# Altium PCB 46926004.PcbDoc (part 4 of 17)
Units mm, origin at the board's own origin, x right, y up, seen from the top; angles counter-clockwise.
Board outline 250 x 200 mm, 6 copper layers (Top Layer, INT1_GND, INT2_SIG, INT3_SIG, INT4_GND, Bottom Layer), stack 1.71 mm thick; 1450 components, 1293 nets, 5656 pads, 2307 vias.
Unrouted connection lines stored in the file: 2.
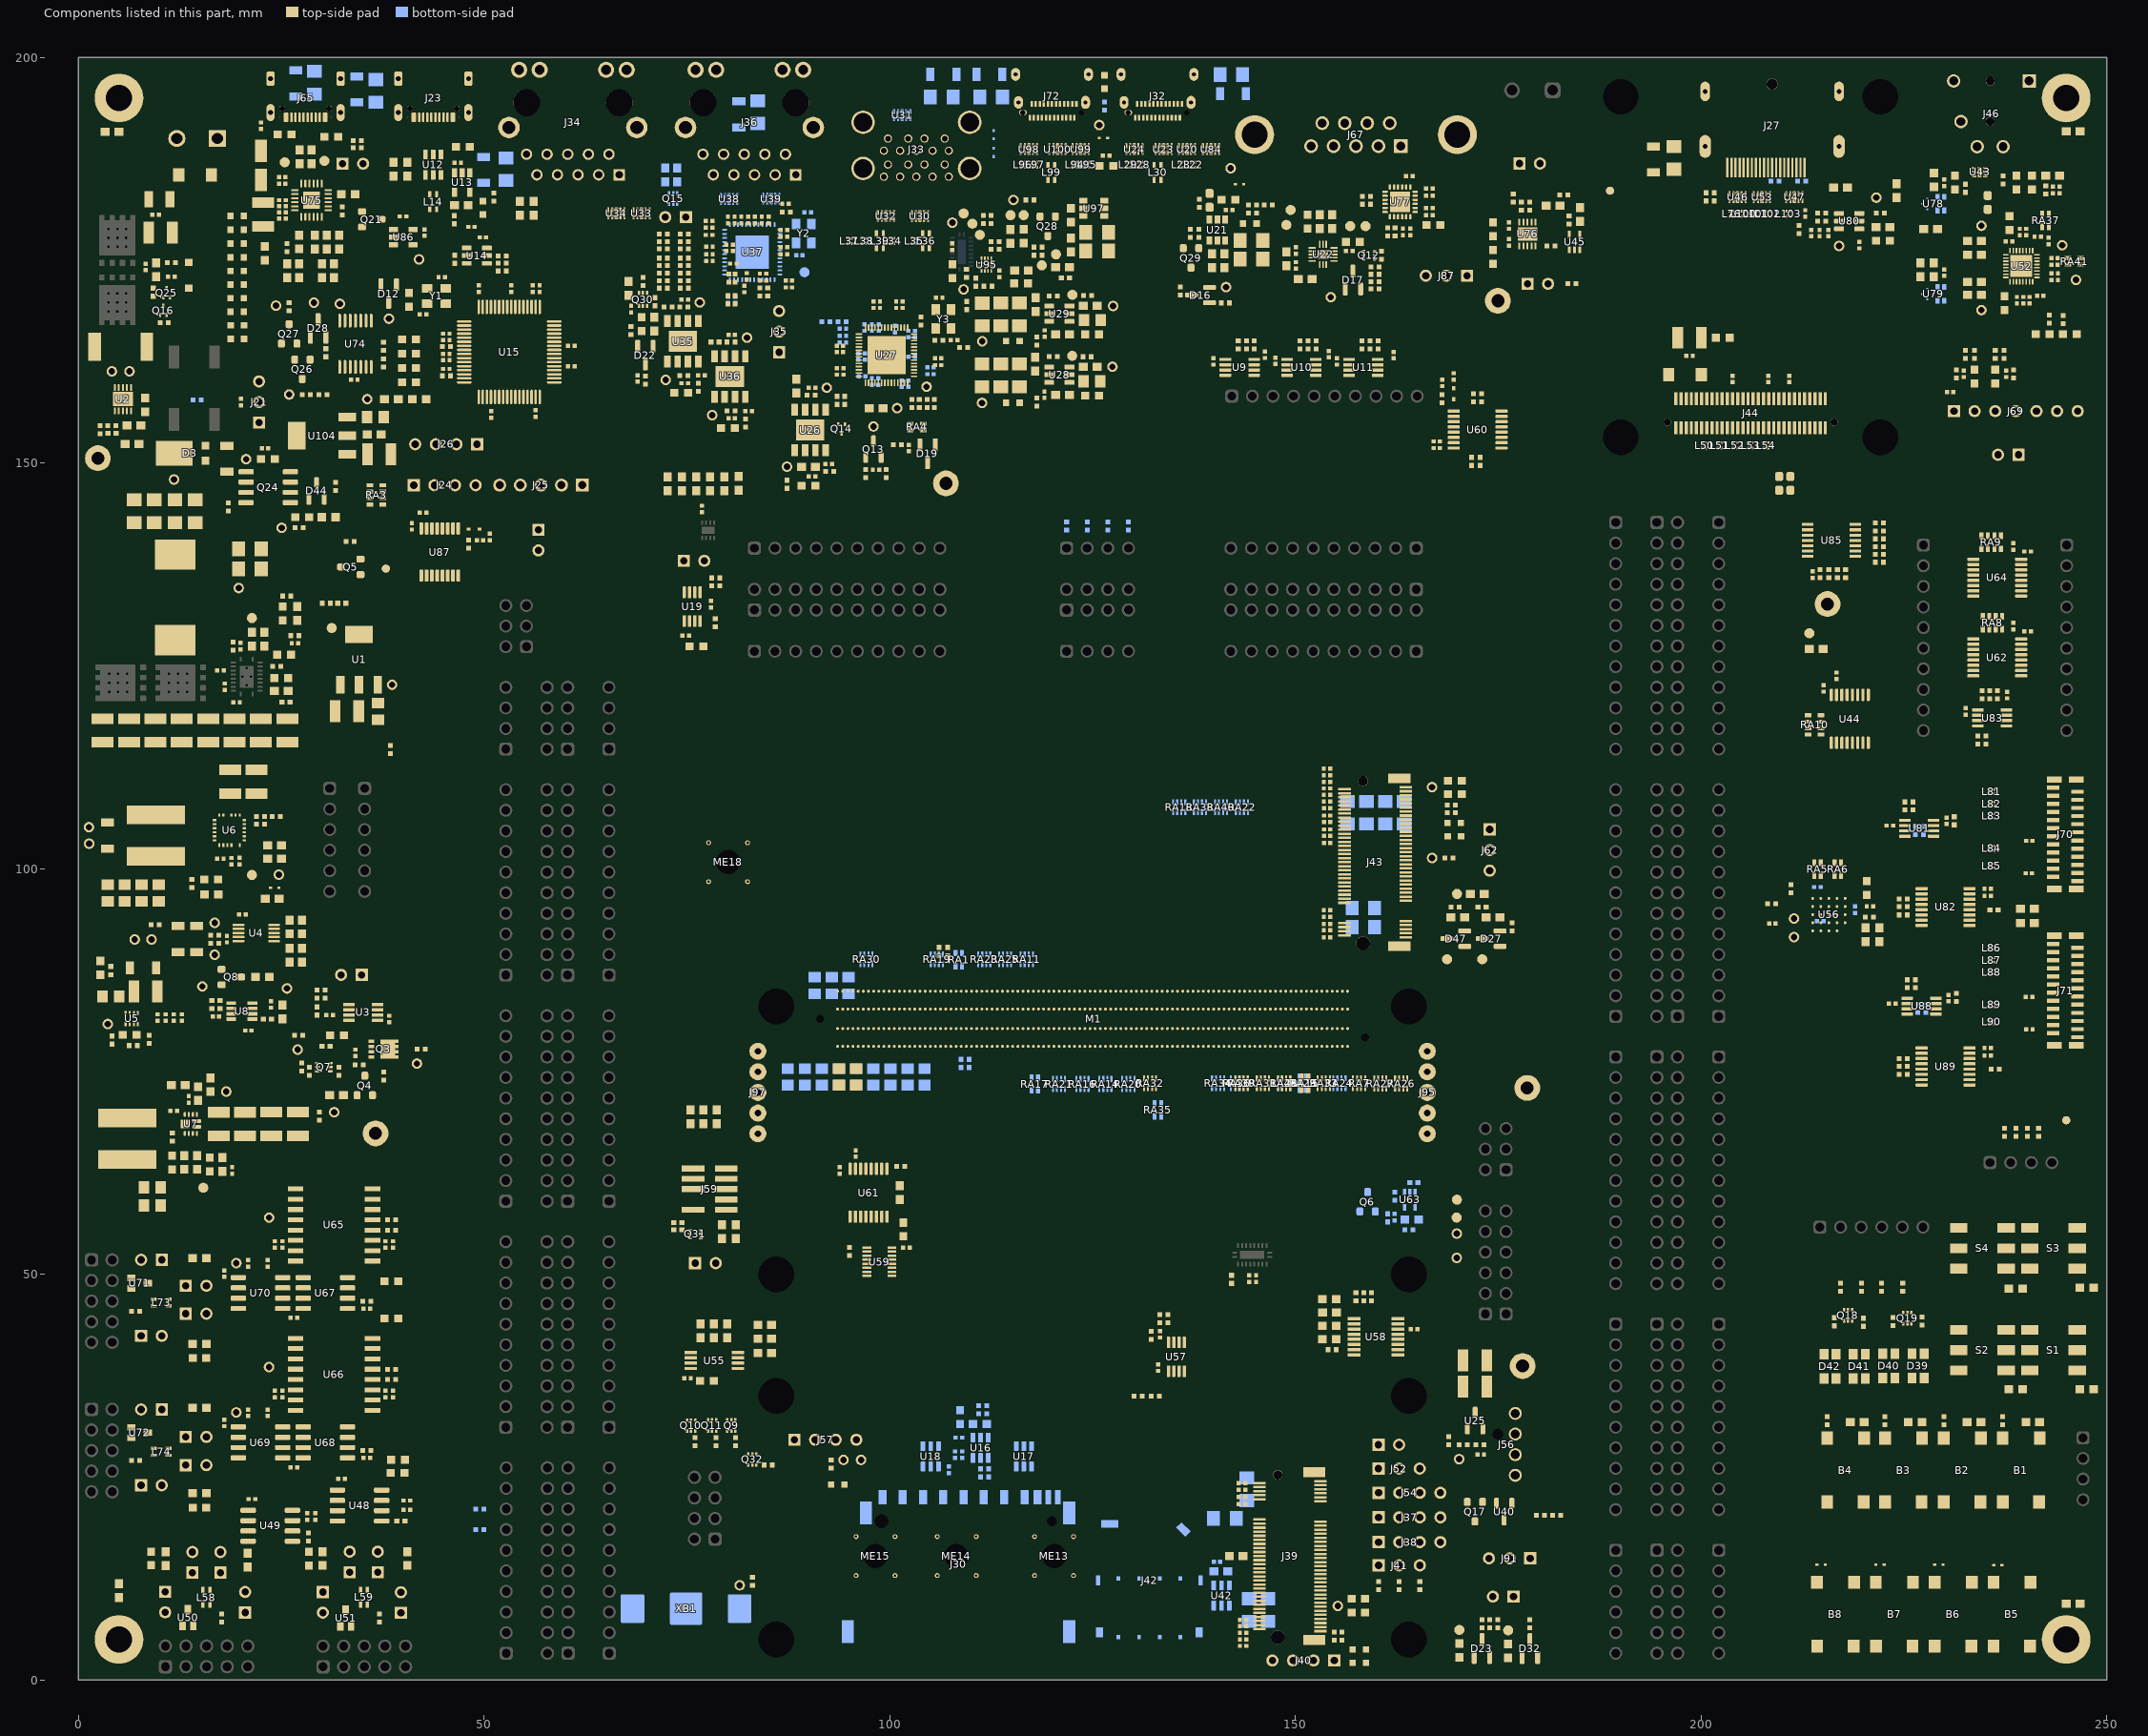
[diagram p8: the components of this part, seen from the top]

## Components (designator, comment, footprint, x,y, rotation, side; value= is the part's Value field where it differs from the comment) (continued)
XB1 "3030TR" T_KEYSTONE_3030 74.9,8.8 r0 bottom locked
Y1 "0986-Xtal 12MHz 3.2x2.5mm" XTAL_CX3225 44.14,170.6 r0 top value="12 MHz"
Y2 "0987-Xtal 25MHz 3.2x2.5mm" XTAL_CX3225 89.397,178.29 r270 bottom value="25 MHz"
Y3 "0987-Xtal 25MHz 3.2x2.5mm" XTAL_CX3225 106.617,167.768 r90 top value="25 MHz"

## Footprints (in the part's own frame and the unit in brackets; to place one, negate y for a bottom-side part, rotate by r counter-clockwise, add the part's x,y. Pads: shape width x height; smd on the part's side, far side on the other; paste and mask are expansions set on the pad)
3M-SJ61A3 [mm] "BUMPER CYLIN 0.375\"(9.53mm) DIA BLK, Thickness: 0.250\" (6.35mm)"
  silkscreen extent -4.67,-4.67 4.85,4.85, body extent -4.76,-4.76 4.76,4.76, height 6.38
4-PLCC [mm] "LED RGB DIFFUSED 4PLCC SMD 3.2 x 2.8 x 1.9 mm"
  rect 1.1x1.3 smd: 1(-0.75,-1.5) 2(-0.75,1.5) 3(0.75,1.5) 4(0.75,-1.5)
  silkscreen extent -1.66,-1.56 1.4,0.51, body extent -1.39,-1.75 1.41,1.75, height 1.9
"10-DFN (3X3)_ADI" [mil] "10-Lead Plastic DFN (3mm ? 3mm), 10-WFDFN Exposed Pad"
  rect 32x10 smd paste+0 mask+0: 1(-57,39.37) 2(-57,19.68) 3(-57,0) 4(-57,-19.69) 5(-57,-39.37) 6(57,-39.37) 7(57,-19.69) 8(57,0) 9(57,19.68) 10(57,39.37)
  rect 69x98 smd paste+0 mask+0: 11(0,0)
  silkscreen extent -93,-66 66,66, body extent -59,-59 59,59, height 30
10-UFDFN [mm] "TVS Diode Surface Mount U-DFN2510-10 (2.5x1.0mm)"
  rrect50% 0.625x0.25 smd mask+0.05: 1(-0.417,1) 2(-0.417,0.5) 4(-0.417,-0.5) 5(-0.417,-1) 6(0.417,-1) 7(0.417,-0.5) 9(0.417,0.5) 10(0.417,1)
  rrect50% 0.7x0.45 smd mask+0.102: 3(-0.375,0)
  rrect50% 0.575x0.45 smd mask+0.102: 8(0.442,0)
  silkscreen extent -1.08,-1.35 0.56,1.36, body extent -0.5,-1.25 0.5,1.25, height 0.5
"10-VSON (3X3)" [mil] "10-VFDFN Exposed Pad, DRC (TI)"
  rect 32x10 smd paste+0 mask+0: 1(-57,39.37) 2(-57,19.68) 3(-57,0) 4(-57,-19.68) 5(-57,-39.37) 6(57,-39.37) 7(57,-19.68) 8(57,0) 9(57,19.68) 10(57,39.37)
  rect 65x95 smd paste-47 mask-47: 11(0,0)
  silkscreen extent -90,-66 66,66, body extent -59,-59 59,59, height 39
"11-VQFN-HR (2.5X2)" [mm] "2.0-mm x 2.5-mm VQFN HotRod Package (TI)"
  rrect40% 0.55x0.25 smd mask+0: 1(-1.175,0.75) 2(-1.175,0.25) 3(-1.175,-0.25) 4(-1.175,-0.75) 7(1.175,-0.75) 8(1.175,-0.25) 9(1.175,0.25) 10(1.175,0.75)
  rrect45% 0.45x1.1 smd paste-2 mask+0: 5(-0.35,-0.7) 6(0.35,-0.7)
  rrect19% 1.1x1.1 smd paste-2 mask+0: 11(0,0.7)
  silkscreen extent -1.89,-1.2 1.25,1.2, body extent -1.25,-1 1.25,1, height 1
"12-X2QFN (1.6X1.6)" [mm] "12-XFQFN 1.60 mm ? 1.60 mm, RWB0012A (TI)"
  rrect50% 0.7x0.2 smd paste+0 mask+0.051: 1(-0.65,0.2) 2(-0.65,-0.2) 7(0.65,-0.2) 8(0.65,0.2)
  rrect50% 0.2x0.5 smd paste+0 mask+0.051: 3(-0.6,-0.75) 4(-0.2,-0.75) 5(0.2,-0.75) 6(0.6,-0.75) 9(0.6,0.75) 10(0.2,0.75) 11(-0.2,0.75) 12(-0.6,0.75)
  silkscreen extent -0.96,-0.91 0.92,0.91, body extent -0.8,-0.8 0.8,0.8, height 0.4
16-SSOP_DBQ_TI [mm] "16-SSOP (0.154\", 3.90mm Width), MO-137"
  rect 1.6x0.41 smd: 1(-2.7,2.223) 2(-2.7,1.588) 3(-2.7,0.953) 4(-2.7,0.317) 5(-2.7,-0.318) 6(-2.7,-0.953) 7(-2.7,-1.588) 8(-2.7,-2.223) 9(2.7,-2.223) 10(2.7,-1.588) 11(2.7,-0.953) 12(2.7,-0.317) 13(2.7,0.318) 14(2.7,0.953) 15(2.7,1.588) 16(2.7,2.223)
  silkscreen extent -1.55,-2.49 1.55,2.49, body extent -3,-2.45 3,2.45, height 1.75
"56-VQFN (7X7)" [mm] "56-VFQFN Exposed Pad, 0.4 mm pitch"
  rrect50% 0.808x0.204 smd paste+0 mask+0: 1(-3.401,2.6) 2(-3.401,2.2) 3(-3.401,1.8) 4(-3.401,1.4) 5(-3.401,1) 6(-3.401,0.6) 7(-3.401,0.2) 8(-3.401,-0.2) 9(-3.401,-0.6) 10(-3.401,-1) 11(-3.401,-1.4) 12(-3.401,-1.8) 13(-3.401,-2.2) 14(-3.401,-2.6) 29(3.401,-2.6) 30(3.401,-2.2) 31(3.401,-1.8) 32(3.401,-1.4) 33(3.401,-1) 34(3.401,-0.6) 35(3.401,-0.2) 36(3.401,0.2) 37(3.401,0.6) 38(3.401,1) 39(3.401,1.4) 40(3.401,1.8) 41(3.401,2.2) 42(3.401,2.6)
  rrect50% 0.204x0.808 smd paste+0 mask+0: 15(-2.6,-3.401) 16(-2.2,-3.401) 17(-1.8,-3.401) 18(-1.4,-3.401) 19(-1,-3.401) 20(-0.6,-3.401) 21(-0.2,-3.401) 22(0.2,-3.401) 23(0.6,-3.401) 24(1,-3.401) 25(1.4,-3.401) 26(1.8,-3.401) 27(2.2,-3.401) 28(2.6,-3.401) 43(2.6,3.401) 44(2.2,3.401) 45(1.8,3.401) 46(1.4,3.401) 47(1,3.401) 48(0.6,3.401) 49(0.2,3.401) 50(-0.2,3.401) 51(-0.6,3.401) 52(-1,3.401) 53(-1.4,3.401) 54(-1.8,3.401) 55(-2.2,3.401) 56(-2.6,3.401)
  rect 4.699x4.699 smd paste-2.349 mask+0: 57(0,0)
  silkscreen extent -4.24,-4.21 4.21,4.21, body extent -3.5,-3.5 3.5,3.5, height 0.99
AMPHENOL_12401826E412A [mm]
  round 0.325 hole 0.65 unplated: 0(-3.6,2.02)
  oval 0.95x0.65 hole 0.65 slot 0.95 at 0 deg unplated: 0(3.6,2.02)
  rect 0.3x0.7 smd: A1(-2.75,2.68) A2(-2.25,2.68) A3(-1.75,2.68) A4(-1.25,2.68) A5(-0.75,2.68) A6(-0.25,2.68) A7(0.25,2.68) A8(0.75,2.68) A9(1.25,2.68) A10(1.75,2.68) A11(2.25,2.68) A12(2.75,2.68) B1(2.5,0.98) B2(2,0.98) B3(1.5,0.98) B4(1,0.98) B5(0.5,0.98) B6(0,0.98) B7(-0.5,0.98) B8(-1,0.98) B9(-1.5,0.98) B10(-2,0.98) B11(-2.5,0.98) B12(-3,0.98)
  oval 1.1x1.6 hole 0.5 slot 1.1 at 90 deg paste+0: SH1(-4.13,0.77) SH3(4.49,-2.68) SH4(-4.49,-2.68)
  oval 1.1x1.55 hole 0.5 slot 1.1 at 90 deg paste+0: SH2(4.13,0.77)
  Top Layer keep-out region: -3.75,-5.22 3.75,-5.22 3.75,-0.25 -3.75,-0.25
  silkscreen extent -4.6,-4.33 4.6,3.58, body extent -4.61,-7.56 4.59,2.94, height 3.2
AMPHENOL_MDT275B03001_TYPE_3052 [mm] "PCIe M.2 Connectors, Storage and Server Connector, P=0.5mm, H=2.75mm, Key B, Gold Plating"
  rect 0.3x1.55 smd mask+0.05: 1(-9.25,3.775) 2(-9,-3.775) 3(-8.75,3.775) 4(-8.5,-3.775) 5(-8.25,3.775) 6(-8,-3.775) 7(-7.75,3.775) 8(-7.5,-3.775) 9(-7.25,3.775) 10(-7,-3.775) 11(-6.75,3.775) 20(-4.5,-3.775) 21(-4.25,3.775) 22(-4,-3.775) 23(-3.75,3.775) 24(-3.5,-3.775) 25(-3.25,3.775) 26(-3,-3.775) 27(-2.75,3.775) 28(-2.5,-3.775) 29(-2.25,3.775) 30(-2,-3.775) 31(-1.75,3.775) 32(-1.5,-3.775) 33(-1.25,3.775) 34(-1,-3.775) 35(-0.75,3.775) 36(-0.5,-3.775) 37(-0.25,3.775) 38(0,-3.775) 39(0.25,3.775) 40(0.5,-3.775) 41(0.75,3.775) 42(1,-3.775) 43(1.25,3.775) 44(1.5,-3.775) 45(1.75,3.775) 46(2,-3.775) 47(2.25,3.775) 48(2.5,-3.775) 49(2.75,3.775) 50(3,-3.775) 51(3.25,3.775) 52(3.5,-3.775) 53(3.75,3.775) 54(4,-3.775) 55(4.25,3.775) 56(4.5,-3.775) 57(4.75,3.775) 58(5,-3.775) 59(5.25,3.775) 60(5.5,-3.775) 61(5.75,3.775) 62(6,-3.775) 63(6.25,3.775) 64(6.5,-3.775) 65(6.75,3.775) 66(7,-3.775) 67(7.25,3.775) 68(7.5,-3.775) 69(7.75,3.775) 70(8,-3.775) 71(8.25,3.775) 72(8.5,-3.775) 73(8.75,3.775) 74(9,-3.775) 75(9.25,3.775)
  rect 1.2x2.75 smd mask+0.05: P1(-10.35,3) P2(10.35,3)
  round 1.15 hole 1.15 unplated: ""(-10,-1.5)
  round 1.65 hole 1.65 unplated: ""(10,-1.5)
  silkscreen extent -15,-51.75 15,4.9, body extent -15,-41.75 15,4.2, height 3.19
AMPHENOL_MDT420M01501 [mm] "CONN M.2 Gen 5 FEMALE 75POS 0.020 GOLD H=4.2mm"
  rect 0.3x1.55 smd mask+0.05: 1(-9.25,3.775) 2(-9,-3.775) 3(-8.75,3.775) 4(-8.5,-3.775) 5(-8.25,3.775) 6(-8,-3.775) 7(-7.75,3.775) 8(-7.5,-3.775) 9(-7.25,3.775) 10(-7,-3.775) 11(-6.75,3.775) 12(-6.5,-3.775) 13(-6.25,3.775) 14(-6,-3.775) 15(-5.75,3.775) 16(-5.5,-3.775) 17(-5.25,3.775) 18(-5,-3.775) 19(-4.75,3.775) 20(-4.5,-3.775) 21(-4.25,3.775) 22(-4,-3.775) 23(-3.75,3.775) 24(-3.5,-3.775) 25(-3.25,3.775) 26(-3,-3.775) 27(-2.75,3.775) 28(-2.5,-3.775) 29(-2.25,3.775) 30(-2,-3.775) 31(-1.75,3.775) 32(-1.5,-3.775) 33(-1.25,3.775) 34(-1,-3.775) 35(-0.75,3.775) 36(-0.5,-3.775) 37(-0.25,3.775) 38(0,-3.775) 39(0.25,3.775) 40(0.5,-3.775) 41(0.75,3.775) 42(1,-3.775) 43(1.25,3.775) 44(1.5,-3.775) 45(1.75,3.775) 46(2,-3.775) 47(2.25,3.775) 48(2.5,-3.775) 49(2.75,3.775) 50(3,-3.775) 51(3.25,3.775) 52(3.5,-3.775) 53(3.75,3.775) 54(4,-3.775) 55(4.25,3.775) 56(4.5,-3.775) 57(4.75,3.775) 58(5,-3.775) 67(7.25,3.775) 68(7.5,-3.775) 69(7.75,3.775) 70(8,-3.775) 71(8.25,3.775) 72(8.5,-3.775) 73(8.75,3.775) 74(9,-3.775) 75(9.25,3.775)
  rect 1.2x2.75 smd: SH1(-10.35,3) SH2(10.35,3)
  round 1.2 hole 1.2 unplated: ""(-10,-1.5)
  round 1.7 hole 1.7 unplated: ""(10,-1.5)
  silkscreen extent -11,-79.75 11,5.18, body extent -11,-79.75 11,3.95, height 4.65
C0402_CAPC1005L [mm] "Chip Capacitor, Body 1.0x0.5mm, IPC High Density"
  rect 0.52x0.52 smd: 1(-0.4,0) 2(0.4,0)
  body extent -0.52,-0.27 0.52,0.28, height 0.54
C/0603 [mm] "CAP CER 0603 (1608 Metric)"
  rect 1x0.95 smd: 1(-0.85,0) 2(0.85,0)
  silkscreen extent -1.58,-0.7 1.3,0.7, body extent -0.8,-0.4 0.8,0.4, height 0.8
C/0805 [mm] "CAP CER 0805 (2012 Metric)"
  rect 1.3x1.5 smd: 1(-1.025,0) 2(1.025,0)
  silkscreen extent -1.9,-1 1.5,1, body extent -1,-0.64 1,0.64, height 1.3
C/1206 [mm] "CAP 1206 (3216 Metric)"
  rect 1.6x1.8 smd: 1(-1.4,0) 2(1.4,0)
  silkscreen extent -2.45,-1.15 2.1,1.15, body extent -1.85,-0.97 1.85,0.97, height 1.84
CAPC3225N [mm] "Chip Capacitor, Body 3.2x2.5mm (1210), IPC Medium Density"
  rect 1.3x2.7 smd: 1(-1.45,0) 2(1.45,0)
  silkscreen extent -0.4,-1.25 0.4,1.25, body extent -1.6,-1.25 1.6,1.25, height 2.5
COIL0302 [mm] "0302 (0806 Metric), 4 Lead"
  rect 0.3x0.35 smd: 1(-0.25,-0.325) 2(0.25,-0.325) 3(0.25,0.325) 4(-0.25,0.325)
  silkscreen extent -0.61,-0.81 0.61,0.34, body extent -0.43,-0.33 0.43,0.33, height 0.5
COMMON_CHOKE_BOURNS_SRF2012-900YA [mm] "2.0x1.2x1.2mm"
  rect 0.75x0.4 smd: 1(-0.925,0.425) 2(0.925,0.425) 3(0.925,-0.425) 4(-0.925,-0.425)
  silkscreen extent -1.67,-0.58 0.3,0.58, body extent -1,-0.6 1,0.6, height 1.2
CON_HDR1X2 [mm] "Connector; Header with 3D model; 2 Position"
  rect 1.5x1.5 hole 0.9 mask+0.05: 1(-1.27,0)
  round 1.5 hole 0.9 mask+0.05: 2(1.27,0)
  silkscreen extent -2.54,-1.27 2.54,1.27, body extent -2.54,-1.27 2.54,1.27, height 7.64
CON_HDR1X3 [mm] "Connector; Header; 3 Position"
  rect 1.5x1.5 hole 0.9: 1(-2.54,0)
  round 1.5 hole 0.9: 2(0,0) 3(2.54,0)
  silkscreen extent -3.81,-1.27 3.75,1.27, body extent -3.81,-1.2 3.81,1.2, height 8.38
CONN_47053-1000_MOL [mm]
  round 0 hole 1.3 unplated paste-2539.97 mask+0.75: 0(1.27,1.08)
  round 1.6 hole 1.1 paste-2539.97 mask+0.1: 1(-3.81,-1.08) 2(-1.27,-1.08) 3(1.27,-1.08) 4(3.81,-1.08)
  silkscreen extent -6.03,-4.51 5.23,1.59, body extent -5.1,-4.38 5.1,1.46, height 10.5
CUI_SJ-43515TS [mm] "3.5 mm, Stereo, Right Angle, Through Hole, 4 Conductors, 1 Internal Tip Switches, Audio Jack Connector"
  rect 1.65x1.65 / inner round 1.65 / far side rect 1.65x1.65 hole 1.1: 1(-2.6,4.8)
  round 1.65 hole 1.1: 2(2.4,-3.6) 3(5.5,1.6) 4(-2.6,-4.5) 5(5.5,-1.6)
  round 1.1 hole 1.1 unplated: ""(-2.6,0) ""(2.4,0)
  silkscreen extent -5.05,-5.47 6.3,5.48, body extent -7.95,-5.48 6.05,4.72, height 5.29
DLC0008A [mm]
  rect 0.55x0.25 smd paste+0 mask+0.051: 1(-0.675,0.75) 2(-0.675,0.25) 3(-0.675,-0.25) 4(-0.675,-0.75) 5(0.675,-0.75) 6(0.675,-0.25) 7(0.675,0.25) 8(0.675,0.75)
  silkscreen extent -1.06,-1.15 0.75,1.26, body extent -0.76,-0.99 0.74,1.01, height 1
DMP3008 [mm] "POWERDI(R)3333-8"
  rect 1.85x2.37 smd: D(0.5,0)
  rect 0.7x0.42 smd: D(1.5,-0.975) D(1.5,-0.325) D(1.5,0.325) D(1.5,0.975) G(-1.5,-0.975) S(-1.5,-0.325) S(-1.5,0.325) S(-1.5,0.975)
  silkscreen extent -2.33,-1.2 -0.7,1.2, body extent -1.65,-1.65 1.65,1.65, height 0.9
"DSUB_A-DS 09 A/KG-T2S" [mm] "Connector; D Subminiature; 9 Position; Right Angle; Pitch 1.385 mm"
  rect 1.69x1.69 hole 1.1: 1(-5.54,1.42)
  round 1.69 hole 1.1: 2(-2.77,1.42) 3(0,1.42) 4(2.77,1.42) 5(5.54,1.42) 6(-4.155,-1.42) 7(-1.385,-1.42) 8(1.385,-1.42) 9(4.155,-1.42)
  round 4.8 hole 3.2: 10(-12.495,0) 11(12.495,0)
  silkscreen extent -15.41,-6.46 15.4,2.94, body extent -15.41,-15.66 15.4,2.94, height 12.57
EATON_EXL1V0705-4R7-R [mm] "8.40mm x 8.00mm x 5mm"
  rect 2.3x7.2 smd: 1(-2.55,0) 2(2.55,0)
  silkscreen extent -4.15,-4.35 4.15,4.36, body extent -4.15,-4.36 4.15,4.36, height 5.01
EXB34V [mm] "Chip Resistor Array, (0603x2); SM; 4 Leads; Body 1.80 x 1.75 mm (LxW max)"
  rect 0.8x0.5 smd: 1(-0.8,0.4) 2(-0.8,-0.4) 3(0.8,-0.4) 4(0.8,0.4)
  silkscreen extent -0.87,-0.9 0.87,0.95, body extent -0.8,-0.8 0.8,0.8, height 0.53
FB_35F0121-0SR-10 [mm] "FERRITE BEAD 1612 (4131 Metric)"
  rect 2.77x1.47 smd: 1(-1.79,0) 2(1.79,0)
  silkscreen extent -2.03,-1.53 2.03,1.53, body extent -2.54,-1.53 2.54,1.53, height 3.05
FID_40X120_RND [mm]
  round 1 smd paste-1 mask+0.8: 1(0,0)
  Top Layer keep-out circle w0.05: c0,0 r1.3
FUSE_1206_(3216) [mm] "FUSE SMD 1206 (3216 Metric)"
  rect 1.1x2 smd paste+0 mask+0: 1(-1.302,0) 2(1.302,0)
  Top Layer keep-out region: -0.6,-0.95 -0.6,0.95 0.6,0.95 0.6,-0.95
  silkscreen extent -0.42,-0.93 0.42,0.93, body extent -1.59,-0.76 1.59,0.76, height 0.54
GCT_USB4105GFA120 [mm] "USB-C (USB TYPE-C) USB 2.0 Receptacle Connector 24 (16+8 Dummy) Position Surface Mount, Right Angle; Through Hole"
  round 0.025 smd mask+0.05: A1/B12(-3.2,2.378) B1/A12(3.2,2.378)
  rrect50% 0.6x1.15 smd mask+0.05: A4/B9(-2.4,2.378) B4/A9(2.4,2.378)
  rrect50% 0.3x1.15 smd mask+0.05: A5(-1.25,2.378) A6(-0.25,2.378) A7(0.25,2.378) A8(1.25,2.378) B5(1.75,2.378) B6(0.75,2.378) B7(-0.75,2.378) B8(-1.75,2.378)
  oval 1x2.1 hole 0.6 slot 1.7 at 90 deg paste+0 mask+0.1: SH1(-4.32,1.803) SH2(4.32,1.803)
  rrect50% 1x1.8 hole 0.6 slot 1.4 at 90 deg paste+0 mask+0.1: SH3(-4.32,-2.377) SH4(4.32,-2.377)
  round 0.7 hole 0.7 unplated mask+0.1: ""(-2.89,1.303) ""(2.89,1.303)
  Top Layer region: 3.456,1.846 3.489,1.895 3.5,1.953 3.5,1.953 3.5,2.803 3.489,2.86 3.456,2.909 3.456,2.909 3.407,2.941 3.35,2.953 3.35,2.953 3.05,2.953 2.993,2.941 2.944,2.909 2.944,2.909 2.911,2.86 2.9,2.803 2.9,2.803 2.9,1.953 2.911,1.899 2.941,1.853 2.941,1.853 2.998,1.853 3.063,1.84 3.119,1.803 3.119,1.803 3.35,1.803 3.408,1.814 3.456,1.846
  Top Layer region: -3.456,1.846 -3.489,1.895 -3.5,1.953 -3.5,1.953 -3.5,2.803 -3.489,2.86 -3.456,2.909 -3.456,2.909 -3.407,2.941 -3.35,2.953 -3.35,2.953 -3.05,2.953 -2.993,2.941 -2.944,2.909 -2.944,2.909 -2.911,2.86 -2.9,2.803 -2.9,2.803 -2.9,1.953 -2.911,1.899 -2.941,1.853 -2.941,1.853 -2.998,1.853 -3.063,1.84 -3.119,1.803 -3.119,1.803 -3.35,1.803 -3.408,1.814 -3.456,1.846
  silkscreen extent -4.47,-4.77 4.47,3.72, body extent -4.47,-4.98 4.47,2.72, height 3.26
HDR1X2 [mm] "PCB header; 2 Position"
  rect 1.5x1.5 hole 0.9 mask+0.05: 1(-1.27,0)
  round 1.5 hole 0.9 mask+0.05: 2(1.27,0)
  silkscreen extent -2.54,-1.27 2.54,1.27
HDR1X3 [mm] "Connector; Header; 3 Position"
  rect 1.5x1.5 hole 0.9: 1(-2.54,0)
  round 1.5 hole 0.9: 2(0,0) 3(2.54,0)
  silkscreen extent -3.81,-1.27 3.75,1.27
HDR1X4 [mm] "Connector; Header; 4 Position"
  rect 1.5x1.5 hole 0.9: 1(-3.81,0)
  round 1.5 hole 0.9: 2(-1.27,0) 3(1.27,0) 4(3.81,0)
  silkscreen extent -5.08,-1.27 5.08,1.27
HDR1X5 [mil] "Header; 5 Pos"
  rect 63x63 hole 39.37: 1(-200,0)
  round 63 hole 39.37: 2(-100,0) 3(0,0) 4(100,0) 5(200,0)
  silkscreen extent -250,-50 250,50
HDR1X7 [mm] "Connector; Header; 7 Position"
  rect 1.5x1.5 hole 0.9: 1(-8.89,0)
  round 1.5 hole 0.9: 2(-6.35,0) 3(-3.81,0) 4(-1.27,0) 5(1.27,0) 6(3.81,0) 7(6.35,0)
  silkscreen extent -10.16,-1.27 7.62,1.27
HIROSE_FH12-24S-0.5SVA(54) [mm] "Toradex pinout - Reversed 3D for Toradex projects"
  rect 0.52x1.5 smd: 1(5.75,1.5) 2(5.25,-1.5) 3(4.75,1.5) 4(4.25,-1.5) 5(3.75,1.5) 6(3.25,-1.5) 7(2.75,1.5) 8(2.25,-1.5) 9(1.75,1.5) 10(1.25,-1.5) 11(0.75,1.5) 12(0.25,-1.5) 13(-0.25,1.5) 14(-0.75,-1.5) 15(-1.25,1.5) 16(-1.75,-1.5) 17(-2.25,1.5) 18(-2.75,-1.5) 19(-3.25,1.5) 20(-3.75,-1.5) 21(-4.25,1.5) 22(-4.75,-1.5) 23(-5.25,1.5) 24(-5.75,-1.5)
  rect 0.8x1.8 smd: MTG(-6.75,-1.35) MTG(-6.75,1.35) MTG(6.75,-1.35) MTG(6.75,1.35)
  silkscreen extent -7.81,-2.46 7.81,3.5, body extent -7.71,-1.91 7.69,1.89, height 5.45
IC-CYPRESS-CYPD3177-24LQXQ [mm]
  rrect30% 0.9x0.25 smd mask+0.05: 1(-2.05,1.25) 2(-2.05,0.75) 3(-2.05,0.25) 4(-2.05,-0.25) 5(-2.05,-0.75) 6(-2.05,-1.25) 13(2.05,-1.25) 14(2.05,-0.75) 15(2.05,-0.25) 16(2.05,0.25) 17(2.05,0.75) 18(2.05,1.25)
  rrect30% 0.25x0.9 smd mask+0.05: 7(-1.25,-2.05) 8(-0.75,-2.05) 9(-0.25,-2.05) 10(0.25,-2.05) 11(0.75,-2.05) 12(1.25,-2.05) 19(1.25,2.05) 20(0.75,2.05) 21(0.25,2.05) 22(-0.25,2.05) 23(-0.75,2.05) 24(-1.25,2.05)
  rect 2.1x2.1 smd paste-5 mask+0.05: 25(0,0)
  silkscreen extent -2.68,-2.2 2.2,2.2, body extent -2.05,-2.05 2.05,2.05, height 0.6
IND_SRP1265A-LF_BRN [mm] "13.50mm x 12.50mm"
  rect 3.75x5 smd: 1(-5.273,0) 2(5.273,0)
  Top Layer keep-out region: -6.95,-6.35 6.95,-6.35 6.95,-2.75 3.15,-2.75 3.15,2.75 6.95,2.75 6.95,6.35 -6.95,6.35 -6.95,2.75 -3.15,2.75 -3.15,-2.75 -6.95,-2.75
  silkscreen extent -7.7,-6.53 7.12,6.53, body extent -6.6,-6.25 6.3,6.25, height 6.3
INDC3225N [mm] "Chip Inductor, Body 3.2x2.5mm, IPC Medium Density / 3D - INDC3225x135N"
  rect 1.3x2.7 smd: 1(-1.45,0) 2(1.45,0)
  silkscreen extent -0.4,-1.25 0.4,1.25, body extent -1.6,-1.25 1.6,1.25, height 1.35
LABEL_0.25X0.9IN [mm]
  silkscreen extent 0,0 23.37,6.86
LED-SMT-0603_APT1608CGCK [mm] "LED SMT Green, 2-Leads, Body 1,00x0,80mm, IPC Medium Density"
  rect 0.8x0.8 smd: 1(-0.825,0) 2(0.825,0)
  silkscreen extent -1.5,-0.69 1.68,0.69, body extent -0.8,-0.4 0.8,0.4, height 0.6
LQFP64_N [mm] "Thin QFP, 64-Leads, Body 10x10mm, Pitch 0.5mm, IPC Medium Density"
  oval 1.8x0.3 smd mask+0.05: 1(-5.55,3.75) 2(-5.55,3.25) 3(-5.55,2.75) 4(-5.55,2.25) 5(-5.55,1.75) 6(-5.55,1.25) 7(-5.55,0.75) 8(-5.55,0.25) 9(-5.55,-0.25) 10(-5.55,-0.75) 11(-5.55,-1.25) 12(-5.55,-1.75) 13(-5.55,-2.25) 14(-5.55,-2.75) 15(-5.55,-3.25) 16(-5.55,-3.75) 33(5.55,-3.75) 34(5.55,-3.25) 35(5.55,-2.75) 36(5.55,-2.25) 37(5.55,-1.75) 38(5.55,-1.25) 39(5.55,-0.75) 40(5.55,-0.25) 41(5.55,0.25) 42(5.55,0.75) 43(5.55,1.25) 44(5.55,1.75) 45(5.55,2.25) 46(5.55,2.75) 47(5.55,3.25) 48(5.55,3.75)
  oval 0.3x1.8 smd mask+0.05: 17(-3.75,-5.55) 18(-3.25,-5.55) 19(-2.75,-5.55) 20(-2.25,-5.55) 21(-1.75,-5.55) 22(-1.25,-5.55) 23(-0.75,-5.55) 24(-0.25,-5.55) 25(0.25,-5.55) 26(0.75,-5.55) 27(1.25,-5.55) 28(1.75,-5.55) 29(2.25,-5.55) 30(2.75,-5.55) 31(3.25,-5.55) 32(3.75,-5.55) 49(3.75,5.55) 50(3.25,5.55) 51(2.75,5.55) 52(2.25,5.55) 53(1.75,5.55) 54(1.25,5.55) 55(0.75,5.55) 56(0.25,5.55) 57(-0.25,5.55) 58(-0.75,5.55) 59(-1.25,5.55) 60(-1.75,5.55) 61(-2.25,5.55) 62(-2.75,5.55) 63(-3.25,5.55) 64(-3.75,5.55)
  silkscreen extent -5.67,-5.55 5.55,5.55, body extent -6,-6 6,6, height 1.5
MECH-WURTH-9774005243R [mm]
  round 0.6 hole 0.3: 0(-2.4,-2.4) 0(-2.4,2.4) 0(2.4,-2.4) 0(2.4,2.4)
  round 0.025 smd: 0(2.4,-2.4)
  round 0 hole 3 unplated: M0(0,0)
  Top Layer circle w0.9: c0,0 r2.2
  Top Layer region: -2.4,2.7 -2.515,2.677 -2.612,2.612 -2.677,2.515 -2.7,2.4 -2.7,2.4 -2.7,-2.4 -2.66,-2.55 -2.55,-2.66 -2.4,-2.7 -2.4,-2.7 0,-2.7 0,-1.9 -0.9,-1.9 -1.9,-0.9 -1.9,0.9 -0.9,1.9 0.9,1.9 1.9,0.9 1.9,-0.9 0.9,-1.9 0,-1.9 0,-2.7 2.4,-2.7 2.515,-2.677 2.612,-2.612 2.677,-2.515 2.7,-2.4 2.7,-2.4 2.7,2.4 2.677,2.515 2.612,2.612 2.515,2.677 2.4,2.7 2.4,2.7
  body extent -2.17,-2.16 2.17,2.16, height 0.5
"MICROSD 0787231001" [mm]
  rect 0.94x2.1 smd: 9(-6.98,4.88)
  rect 0.94x1.6 smd rot 45: 9(-6.3,-4.19)
  rect 1.2x0.52 smd: 9(-0.02,-6.31) 9(-0.02,6.31)
  rect 1.2x0.89 smd: 9(6.37,-6.125) 9(6.37,6.125)
  rect 0.52x0.45 smd: C1(6.98,3.81) C2(6.98,1.27) C3(6.98,-1.27) C4(6.98,-3.81) C5(-0.28,3.81) C6(-0.28,1.27) C7(-0.28,-1.27) C8(-0.28,-3.81)
  silkscreen extent -7.35,-6.53 7.45,6.53, body extent -7.33,-6.41 22.55,6.39, height 1.34
MOLEX_47272-0001 [mm] "CONN RCPT DISPLAYPORT 20P SMD RA"
  rect 0.28x2.4 smd: 1(5.5,5.14) 2(5,5.14) 3(4.5,5.14) 4(4,5.14) 5(3.5,5.14) 6(3,5.14) 7(2.5,5.14) 8(2,5.14) 9(1.5,5.14) 10(1,5.14) 11(0.5,5.14) 12(0,5.14) 13(-0.5,5.14) 14(-1,5.14) 15(-1.5,5.14) 16(-2,5.14) 17(-2.5,5.14) 18(-3,5.14) 19(-3.5,5.14) 20(-4,5.14)
  oval 1.4x2.8 hole 0.6 slot 2.2 at 90 deg: S1(-8.25,2.54) S2(8.25,2.54)
  oval 1.2x2.4 hole 0.6 slot 1.7 at 90 deg: S3(-8.25,-4.24) S4(8.25,-4.24)
  round 1.4 hole 1.4 unplated: ""(0,-5.14)
  silkscreen extent -8.45,-7.94 8.45,6.8, body extent -8.89,-9.12 8.89,5.77, height 6.7
MSOP-10 [mm] "10-VSSOP, 10-TFSOP, 10-MSOP (0.118\", 3.00mm Width), 0.5mm pitch, DGS0010A (TI)"
  rrect50% 1.45x0.305 smd: 1(-2.2,1.001) 2(-2.2,0.5) 3(-2.2,0) 4(-2.2,-0.5) 5(-2.2,-1.001) 6(2.2,-1.001) 7(2.2,-0.5) 8(2.2,0) 9(2.2,0.5) 10(2.2,1.001)
  silkscreen extent -2.34,-1.25 1.07,1.59, body extent -2.56,-1.55 2.56,1.55, height 1.03
MTG_HOLE_0.125 [mm] "Mounting hole 0,125\" (3.2 mm)"
  round 6 hole 3.2 paste-2539.97: 0(0,0)
"MTG_POST WURTH 9774050360R" [mm] "Mounting Post Wurth Electronics 9774050360R"
  round 0 hole 4.4 unplated: 0(0,0)
  Top Layer circle w1.3: c0,0 r3.05
  Top Layer keep-out circle w0.05: c0,0 r3.9
  Bottom Layer keep-out circle w0.05: c0,0 r2.45
  body extent -3,-3 2.99,3, height 5
OMRONSW_B3FS-1010P [mil] "SWITCH TACTILE SPST-NO 6.30mm x 6.00mm"
  rect 63x57 smd: 1(155,-90) 2(-154.96,-87.6) 3(155,90) 4(-154.96,89.57)
  silkscreen extent -125,-124 159,124, body extent -157,-124 158,124, height 169
PHOENIX_1923759 [mm] "TERM BLOCK HDR 2POS 90DEG 5MM"
  rect 2.1x2.1 / inner round 2.1 / far side rect 2.1x2.1 hole 1.4: 1(-2.5,0)
  round 2.1 hole 1.4: 2(2.5,0)
  silkscreen extent -6,-9.5 6,2.58, body extent -6,-10 6,2, height 9.14
POGO_821-22-005_MILL_MAX [mm] "821 SPRING-LOADED POGO PIN HEADER STRIP"
  round 2.1 hole 0.8: 1(-5.08,0) 2(-2.54,0) 3(0,0) 4(2.54,0) 5(5.08,0)
  silkscreen extent -6.48,-1.4 6.48,1.4, body extent -6.35,-1.27 6.35,1.27, height 5.99
POWERDI-5_DIO [mil] "Diodes PowerDI5"
  rect 37x39 smd paste+0 mask+0: 1(-111.5,36.22) 2(-111.5,-36.22)
  rect 177x120 smd paste+0 mask+0: 3(41.5,0)
  silkscreen extent -113,-85 113,85, body extent -130,-79 130,79, height 45
PULSE_JXD0-0025NL [mm]
  round 3.25 hole 3.3 unplated: 0(-5.715,-2.415) 0(5.715,-2.415)
  rect 1.4x1.4 hole 0.9: 1(-5.715,6.475)
  round 1.4 hole 0.9: 2(-4.445,3.935) 3(-3.175,6.475) 4(-1.905,3.935) 5(-0.635,6.475) 6(0.635,3.935) 7(1.905,6.475) 8(3.175,3.935) 9(4.445,6.475) 10(5.715,3.935)
  round 2 hole 1.2: 11(-6.63,-6.475) 12(-4.09,-6.475) 13(4.09,-6.475) 14(6.63,-6.475)
  round 2.65 hole 1.6: S(-7.875,0.635) S(7.875,0.635)
  silkscreen extent -7.92,-7.56 7.89,8.18, body extent -9.95,-13.17 10.05,8.18, height 15.5
PW014_N [mm] "TSOP, 14-Leads, Body 5x4.4mm, Pitch 0.65mm, IPC Medium Density"
  oval 1.7x0.35 smd: 1(-2.85,1.95) 2(-2.85,1.3) 3(-2.85,0.65) 4(-2.85,0) 5(-2.85,-0.65) 6(-2.85,-1.3) 7(-2.85,-1.95) 8(2.85,-1.95) 9(2.85,-1.3) 10(2.85,-0.65) 11(2.85,0) 12(2.85,0.65) 13(2.85,1.3) 14(2.85,1.95)
  silkscreen extent -2.97,-2.55 1.6,2.67, body extent -3.19,-2.49 3.21,2.51, height 1.1
QFN4X4-22L_EP2_S_AOS [mil]
  rect 18x10 smd paste+0 mask+0: 1(-71.85,49.25) 2(-71.85,29.55) 3(-71.85,9.85) 4(-71.85,-9.85) 5(-71.85,-29.55) 6(-71.85,-49.25) 12(71.85,-49.25) 13(71.85,-29.55) 14(71.85,-9.85) 15(71.85,9.85) 16(71.85,29.55) 17(71.85,49.25)
  rect 10x13 smd paste-6.5 mask-6.5: 7(-49.25,-74.35) 8(-29.55,-74.35) 9(-9.85,-74.35) 10(29.55,-74.35) 11(49.25,-74.35)
  round 1 smd: 9(-29.55,-13.2) 10(36.4,-13.2)
  rect 10x18 smd paste+0 mask+0: 18(49.25,71.85) 19(29.55,71.85) 20(9.85,71.85) 21(-9.85,71.85) 22(-49.25,71.85)
  Top Layer pour cut-out: -62.99,-68.9 -62.99,62.99 62.99,62.99 62.99,-68.9
  Top Layer region: -44.25,-80.85 -54.25,-80.85 -54.25,-67.55 -51.85,-67.55 -51.85,42.5 -42.5,54.45 -4.85,54.45 -4.85,-80.85 -14.85,-80.85 -14.85,-67.55 -24.55,-67.55 -24.55,-80.85 -34.55,-80.85 -34.55,-67.55 -44.25,-67.55
  Top Layer region: 18.55,54.45 18.55,-67.55 24.55,-67.55 24.55,-80.85 34.55,-80.85 34.55,-67.55 44.25,-67.55 44.25,-80.85 54.25,-80.85 54.25,-67.55 52.25,-67.55 52.25,54.45
  silkscreen extent -97,-91 84,91, body extent -79,-79 79,79, height 39
QFN4X4-24_EP [mm] "24-VQFN (4x4), 24-VFQFN Exposed Pad, Quad Flat No Lead, Plastic; 24 Terminals; Body 4 x 4 mm; Pitch 0.5 mm"
  rect 0.28x0.28 smd: 1(-2.015,1.25) 2(-2.015,0.75) 3(-2.015,0.25) 4(-2.015,-0.25) 5(-2.015,-0.75) 6(-2.015,-1.25) 7(-1.25,-2.015) 8(-0.75,-2.015) 9(-0.25,-2.015) 10(0.25,-2.015) 11(0.75,-2.015) 12(1.25,-2.015) 13(2.015,-1.25) 14(2.015,-0.75) 15(2.015,-0.25) 16(2.015,0.25) 17(2.015,0.75) 18(2.015,1.25) 19(1.25,2.015) 20(0.75,2.015) 21(0.25,2.015) 22(-0.25,2.015) 23(-0.75,2.015) 24(-1.25,2.015)
  oval 0.66x0.28 smd: 1(-1.825,1.25) 2(-1.825,0.75) 3(-1.825,0.25) 4(-1.825,-0.25) 5(-1.825,-0.75) 6(-1.825,-1.25) 13(1.825,-1.25) 14(1.825,-0.75) 15(1.825,-0.25) 16(1.825,0.25) 17(1.825,0.75) 18(1.825,1.25)
  oval 0.28x0.66 smd: 7(-1.25,-1.825) 8(-0.75,-1.825) 9(-0.25,-1.825) 10(0.25,-1.825) 11(0.75,-1.825) 12(1.25,-1.825) 19(1.25,1.825) 20(0.75,1.825) 21(0.25,1.825) 22(-0.25,1.825) 23(-0.75,1.825) 24(-1.25,1.825)
  rect 2.5x2.5 smd paste-1.25: 25(0,0)
  silkscreen extent -2.65,-2.05 2.05,2.05, body extent -2.13,-2.13 2.13,2.13, height 1
QFN40P260X260X40-17N-D [mm] "16-HX2QFN (2.6x2.6), 16-XFQFN Exposed Pad"
  rect 0.85x0.2 smd: 1(-1.35,0.8) 2(-1.35,0.4) 3(-1.35,0) 4(-1.35,-0.4) 5(-1.35,-0.8) 9(1.35,-0.8) 10(1.35,-0.4) 11(1.35,0) 12(1.35,0.4) 13(1.35,0.8)
  rect 0.2x0.85 smd: 6(-0.4,-1.25) 7(0,-1.25) 8(0.4,-1.25) 14(0.4,1.25) 15(0,1.25) 16(-0.4,1.25)
  rect 1.2x1.1 smd: 17(0,0)
  silkscreen extent -1.65,-1.6 1.55,1.6, body extent -1.35,-1.35 1.35,1.35, height 0.4
QFN40P400X400X75_HS-33N [mm] "QFN, 32-Leads, Body 4,00x4,00mm, Pitch 0,40mm, Thermal Pad 2,70x2,70mm, IPC Medium Density"
  oval 0.711x0.2 smd: 1(-1.925,1.4) 2(-1.925,1) 3(-1.925,0.6) 4(-1.925,0.2) 5(-1.925,-0.2) 6(-1.925,-0.6) 7(-1.925,-1) 8(-1.925,-1.4) 17(1.925,-1.4) 18(1.925,-1) 19(1.925,-0.6) 20(1.925,-0.2) 21(1.925,0.2) 22(1.925,0.6) 23(1.925,1) 24(1.925,1.4)
  oval 0.2x0.711 smd: 9(-1.4,-1.925) 10(-1,-1.925) 11(-0.6,-1.925) 12(-0.2,-1.925) 13(0.2,-1.925) 14(0.6,-1.925) 15(1,-1.925) 16(1.4,-1.925) 25(1.4,1.925) 26(1,1.925) 27(0.6,1.925) 28(0.2,1.925) 29(-0.2,1.925) 30(-0.6,1.925) 31(-1,1.925) 32(-1.4,1.925)
  rect 2.7x2.7 smd: 33(0,0)
  silkscreen extent -2.92,-2.15 2.15,2.15, body extent -1.99,-1.99 1.99,1.99, height 0.81
R0402_RESC1005L [mm] "Chip Resistor, Body 1.1x0.5mm, IPC High Density"
  rect 0.6x0.6 smd mask+0.1: 1(-0.5,0) 2(0.5,0)
  body extent -0.5,-0.25 0.5,0.25, height 0.35
R/0603 [mm] "RES 1/10W 0603"
  rect 1.1x1 smd: 1(-0.85,0) 2(0.85,0)
  silkscreen extent -1.65,-0.75 1.65,0.75, body extent -0.8,-0.4 0.8,0.4, height 0.45
R/1206 [mm] "1206 (3216 Metric)"
  rect 1x1.6 smd: 1(-1.6,0) 2(1.6,0)
  silkscreen extent -2.36,-1.09 2.36,1.09, body extent -1.51,-0.77 1.51,0.77, height 0.55
R/2512 [mm] "2512 (6432 Metric)"
  rect 1.55x3.5 smd: 1(-3.225,0) 2(3.225,0)
  silkscreen extent -4.24,-2 4.24,2, body extent -3.2,-1.6 3.2,1.6, height 0.6
RES_4_X_0804 [mm] "RES ARR 4 RES 22 OHM 0804"
  rect 0.75x0.25 smd paste+0 mask+0.05: 1(-0.6,0.75) 2(-0.6,0.25) 3(-0.6,-0.25) 4(-0.6,-0.75) 5(0.6,-0.75) 6(0.6,-0.25) 7(0.6,0.25) 8(0.6,0.75)
  body extent -0.5,-1 0.5,1, height 0.4
RESNET-1206-4 [mm]
  rect 0.5x0.8 smd: 1(-1.2,-0.8) 2(-0.4,-0.8) 3(0.4,-0.8) 4(1.2,-0.8) 5(1.2,0.8) 6(0.4,0.8) 7(-0.4,0.8) 8(-1.2,0.8)
  silkscreen extent -1.75,-0.87 1.7,0.87, body extent -1.6,-0.8 1.6,0.8, height 0.57
RGZ0048B [mm] "48-VQFN (7x7) (RGZ) Exposed Pad with vias"
  oval 0.6x0.24 smd paste+0 mask+0.051: 1(-3.4,2.75) 2(-3.4,2.25) 3(-3.4,1.75) 4(-3.4,1.25) 5(-3.4,0.75) 6(-3.4,0.25) 7(-3.4,-0.25) 8(-3.4,-0.75) 9(-3.4,-1.25) 10(-3.4,-1.75) 11(-3.4,-2.25) 12(-3.4,-2.75) 25(3.4,-2.75) 26(3.4,-2.25) 27(3.4,-1.75) 28(3.4,-1.25) 29(3.4,-0.75) 30(3.4,-0.25) 31(3.4,0.25) 32(3.4,0.75) 33(3.4,1.25) 34(3.4,1.75) 35(3.4,2.25) 36(3.4,2.75)
  oval 0.24x0.6 smd paste+0 mask+0.051: 13(-2.75,-3.4) 14(-2.25,-3.4) 15(-1.75,-3.4) 16(-1.25,-3.4) 17(-0.75,-3.4) 18(-0.25,-3.4) 19(0.25,-3.4) 20(0.75,-3.4) 21(1.25,-3.4) 22(1.75,-3.4) 23(2.25,-3.4) 24(2.75,-3.4) 37(2.75,3.4) 38(2.25,3.4) 39(1.75,3.4) 40(1.25,3.4) 41(0.75,3.4) 42(0.25,3.4) 43(-0.25,3.4) 44(-0.75,3.4) 45(-1.25,3.4) 46(-1.75,3.4) 47(-2.25,3.4) 48(-2.75,3.4)
  rect 4.1x4.1 smd paste-2.037 mask+0.051: 49(0,0)
  silkscreen extent -4.07,-3.72 3.72,3.72, body extent -3.5,-3.5 3.5,3.5, height 1
SAMTEC_APM-100-01.5-L04-0-A [mm] "CARRIER PLUG CONN 0.635MM HDR 400POS SMD - COLUMNS(NO BALLS)"
  round 0.025 on Mech1: 1(-36.1,-3.1) 1(-36.1,-3.1) 1(-36.1,0.475) 1(-36.1,0.475) 1(-35.6,-4.8) 1(-35.6,-4.8) 1(-35.6,-3.1) 1(-35.6,-3.1) 1(-35.6,0.475) 1(-35.6,0.475) 1(-35.6,3.4) 1(-35.6,3.4) 1(-34.2,4.8) 1(-34.2,4.8) 1(-0.5,0) 1(-0.35,0) 1(0,-0.5) 1(0.35,0) 1(34.2,4.8) 1(34.2,4.8) 1(35.6,-3.1) 1(35.6,-0.5) 1(35.6,-4.8) 1(35.6,-4.8) 1(35.6,-3.1) 1(35.6,-0.5) 1(35.6,3.4) 1(35.6,3.4) 1(36.4,-0.5) 1(36.4,-0.5)
  round 0.356 smd paste-2539.97 mask+0.075: A01(31.432,3.4) A02(30.797,3.4) A03(30.162,3.4) A04(29.527,3.4) A05(28.892,3.4) A06(28.258,3.4) A07(27.622,3.4) A08(26.987,3.4) A09(26.352,3.4) A10(25.717,3.4) A11(25.082,3.4) A12(24.447,3.4) A13(23.812,3.4) A14(23.177,3.4) A15(22.543,3.4) A16(21.907,3.4) A17(21.273,3.4) A18(20.637,3.4) A19(20.002,3.4) A20(19.367,3.4) A21(18.732,3.4) A22(18.098,3.4) A23(17.462,3.4) A24(16.828,3.4) A25(16.192,3.4) A26(15.557,3.4) A27(14.922,3.4) A28(14.287,3.4) A29(13.652,3.4) A30(13.018,3.4) A31(12.383,3.4) A32(11.747,3.4) A33(11.112,3.4) A34(10.477,3.4) A35(9.842,3.4) A36(9.207,3.4) A37(8.572,3.4) A38(7.938,3.4) A39(7.302,3.4) A40(6.667,3.4) A41(6.032,3.4) A42(5.397,3.4) A43(4.763,3.4) A44(4.127,3.4) A45(3.492,3.4) A46(2.857,3.4) A47(2.222,3.4) A48(1.587,3.4) A49(0.953,3.4) A50(0.318,3.4) A51(-0.318,3.4) A52(-0.953,3.4) A53(-1.587,3.4) A54(-2.222,3.4) A55(-2.857,3.4) A56(-3.492,3.4) A57(-4.127,3.4) A58(-4.763,3.4) A59(-5.397,3.4) A60(-6.032,3.4) A61(-6.667,3.4) A62(-7.302,3.4) A63(-7.938,3.4) A64(-8.572,3.4) A65(-9.207,3.4) A66(-9.842,3.4) A67(-10.477,3.4) A68(-11.112,3.4) A69(-11.747,3.4) A70(-12.383,3.4) A71(-13.018,3.4) A72(-13.652,3.4) A73(-14.287,3.4) A74(-14.922,3.4) A75(-15.557,3.4) A76(-16.192,3.4) A77(-16.828,3.4) A78(-17.462,3.4) A79(-18.098,3.4) A80(-18.732,3.4) A81(-19.367,3.4) A82(-20.002,3.4) A83(-20.637,3.4) A84(-21.273,3.4) A85(-21.907,3.4) A86(-22.543,3.4) A87(-23.177,3.4) A88(-23.812,3.4) A89(-24.447,3.4) A90(-25.082,3.4) A91(-25.717,3.4) A92(-26.352,3.4) A93(-26.987,3.4) A94(-27.622,3.4) A95(-28.258,3.4) A96(-28.892,3.4) A97(-29.527,3.4) A98(-30.162,3.4) A99(-30.797,3.4) A100(-31.432,3.4) B01(31.432,1.2) B02(30.797,1.2) B03(30.162,1.2) B04(29.527,1.2) B05(28.892,1.2) B06(28.257,1.2) B07(27.622,1.2) B08(26.987,1.2) B09(26.352,1.2) B10(25.717,1.2) B11(25.082,1.2) B12(24.447,1.2) B13(23.812,1.2) B14(23.177,1.2) B15(22.542,1.2) B16(21.907,1.2) B17(21.272,1.2) B18(20.637,1.2) B19(20.002,1.2) B20(19.367,1.2) B21(18.732,1.2) B22(18.097,1.2) B23(17.462,1.2) B24(16.827,1.2) B25(16.192,1.2) B26(15.557,1.2) B27(14.922,1.2) B28(14.287,1.2) B29(13.652,1.2) B30(13.017,1.2) B31(12.382,1.2) B32(11.747,1.2) B33(11.112,1.2) B34(10.477,1.2) B35(9.842,1.2) B36(9.207,1.2) B37(8.572,1.2) B38(7.937,1.2) B39(7.302,1.2) B40(6.667,1.2) B41(6.032,1.2) B42(5.397,1.2) B43(4.762,1.2) B44(4.127,1.2) B45(3.492,1.2) B46(2.857,1.2) B47(2.222,1.2) B48(1.587,1.2) B49(0.952,1.2) B50(0.317,1.2) B51(-0.318,1.2) B52(-0.953,1.2) B53(-1.588,1.2) B54(-2.223,1.2) B55(-2.858,1.2) B56(-3.493,1.2) B57(-4.128,1.2) B58(-4.763,1.2) B59(-5.398,1.2) B60(-6.033,1.2) B61(-6.668,1.2) B62(-7.303,1.2) B63(-7.938,1.2) B64(-8.573,1.2) B65(-9.208,1.2) B66(-9.843,1.2) B67(-10.478,1.2) B68(-11.113,1.2) B69(-11.748,1.2) B70(-12.383,1.2) B71(-13.018,1.2) B72(-13.653,1.2) B73(-14.288,1.2) B74(-14.923,1.2) B75(-15.558,1.2) B76(-16.193,1.2) B77(-16.828,1.2) B78(-17.463,1.2) B79(-18.098,1.2) B80(-18.733,1.2) B81(-19.368,1.2) B82(-20.003,1.2) B83(-20.638,1.2) B84(-21.273,1.2) B85(-21.908,1.2) B86(-22.543,1.2) B87(-23.178,1.2) B88(-23.813,1.2) B89(-24.448,1.2) B90(-25.083,1.2) B91(-25.718,1.2) B92(-26.353,1.2) B93(-26.988,1.2) B94(-27.623,1.2) B95(-28.258,1.2) B96(-28.893,1.2) B97(-29.528,1.2) B98(-30.163,1.2) B99(-30.798,1.2) B100(-31.433,1.2) C01(31.432,-1.2) C02(30.797,-1.2) C03(30.162,-1.2) C04(29.527,-1.2) C05(28.892,-1.2) C06(28.257,-1.2) C07(27.622,-1.2) C08(26.987,-1.2) C09(26.352,-1.2) C10(25.717,-1.2) C11(25.082,-1.2) C12(24.447,-1.2) C13(23.812,-1.2) C14(23.177,-1.2) C15(22.542,-1.2) C16(21.907,-1.2) C17(21.272,-1.2) C18(20.637,-1.2) C19(20.002,-1.2) C20(19.367,-1.2) C21(18.732,-1.2) C22(18.097,-1.2) C23(17.462,-1.2) C24(16.827,-1.2) C25(16.192,-1.2) C26(15.557,-1.2) C27(14.922,-1.2) C28(14.287,-1.2) C29(13.652,-1.2) C30(13.017,-1.2) C31(12.382,-1.2) C32(11.747,-1.2) C33(11.112,-1.2) C34(10.477,-1.2) C35(9.842,-1.2) C36(9.207,-1.2) C37(8.572,-1.2) C38(7.937,-1.2) C39(7.302,-1.2) C40(6.667,-1.2) C41(6.032,-1.2) C42(5.397,-1.2) C43(4.762,-1.2) C44(4.127,-1.2) C45(3.492,-1.2) C46(2.857,-1.2) C47(2.222,-1.2) C48(1.587,-1.2) C49(0.952,-1.2) C50(0.317,-1.2) C51(-0.318,-1.2) C52(-0.953,-1.2) C53(-1.588,-1.2) C54(-2.223,-1.2) C55(-2.858,-1.2) C56(-3.493,-1.2) C57(-4.128,-1.2) C58(-4.763,-1.2) C59(-5.398,-1.2) C60(-6.033,-1.2) C61(-6.668,-1.2) C62(-7.303,-1.2) C63(-7.938,-1.2) C64(-8.573,-1.2) C65(-9.208,-1.2) C66(-9.843,-1.2) C67(-10.478,-1.2) C68(-11.113,-1.2) C69(-11.748,-1.2) C70(-12.383,-1.2) C71(-13.018,-1.2) C72(-13.653,-1.2) C73(-14.288,-1.2) C74(-14.923,-1.2) C75(-15.558,-1.2) C76(-16.193,-1.2) C77(-16.828,-1.2) C78(-17.463,-1.2) C79(-18.098,-1.2) C80(-18.733,-1.2) C81(-19.368,-1.2) C82(-20.003,-1.2) C83(-20.638,-1.2) C84(-21.273,-1.2) C85(-21.908,-1.2) C86(-22.543,-1.2) C87(-23.178,-1.2) C88(-23.813,-1.2) C89(-24.448,-1.2) C90(-25.083,-1.2) C91(-25.718,-1.2) C92(-26.353,-1.2) C93(-26.988,-1.2) C94(-27.623,-1.2) C95(-28.258,-1.2) C96(-28.893,-1.2) C97(-29.528,-1.2) C98(-30.163,-1.2) C99(-30.798,-1.2) C100(-31.433,-1.2) D01(31.432,-3.4) D02(30.797,-3.4) D03(30.162,-3.4) D04(29.527,-3.4) D05(28.892,-3.4) D06(28.257,-3.4) D07(27.622,-3.4) D08(26.987,-3.4) D09(26.352,-3.4) D10(25.717,-3.4) D11(25.082,-3.4) D12(24.447,-3.4) D13(23.812,-3.4) D14(23.177,-3.4) D15(22.542,-3.4) D16(21.907,-3.4) D17(21.272,-3.4) D18(20.637,-3.4) D19(20.002,-3.4) D20(19.367,-3.4) D21(18.732,-3.4) D22(18.097,-3.4) D23(17.462,-3.4) D24(16.827,-3.4) D25(16.192,-3.4) D26(15.557,-3.4) D27(14.922,-3.4) D28(14.287,-3.4) D29(13.652,-3.4) D30(13.017,-3.4) D31(12.382,-3.4) D32(11.747,-3.4) D33(11.112,-3.4) D34(10.477,-3.4) D35(9.842,-3.4) D36(9.207,-3.4) D37(8.572,-3.4) D38(7.937,-3.4) D39(7.302,-3.4) D40(6.667,-3.4) D41(6.032,-3.4) D42(5.397,-3.4) D43(4.762,-3.4) D44(4.127,-3.4) D45(3.492,-3.4) D46(2.857,-3.4) D47(2.222,-3.4) D48(1.587,-3.4) D49(0.952,-3.4) D50(0.317,-3.4) D51(-0.318,-3.4) D52(-0.953,-3.4) D53(-1.588,-3.4) D54(-2.223,-3.4) D55(-2.858,-3.4) D56(-3.493,-3.4) D57(-4.128,-3.4) D58(-4.763,-3.4) D59(-5.398,-3.4) D60(-6.033,-3.4) D61(-6.668,-3.4) D62(-7.303,-3.4) D63(-7.938,-3.4) D64(-8.573,-3.4) D65(-9.208,-3.4) D66(-9.843,-3.4) D67(-10.478,-3.4) D68(-11.113,-3.4) D69(-11.748,-3.4) D70(-12.383,-3.4) D71(-13.018,-3.4) D72(-13.653,-3.4) D73(-14.288,-3.4) D74(-14.923,-3.4) D75(-15.558,-3.4) D76(-16.193,-3.4) D77(-16.828,-3.4) D78(-17.463,-3.4) D79(-18.098,-3.4) D80(-18.733,-3.4) D81(-19.368,-3.4) D82(-20.003,-3.4) D83(-20.638,-3.4) D84(-21.273,-3.4) D85(-21.908,-3.4) D86(-22.543,-3.4) D87(-23.178,-3.4) D88(-23.813,-3.4) D89(-24.448,-3.4) D90(-25.083,-3.4) D91(-25.718,-3.4) D92(-26.353,-3.4) D93(-26.988,-3.4) D94(-27.623,-3.4) D95(-28.258,-3.4) D96(-28.893,-3.4) D97(-29.528,-3.4) D98(-30.163,-3.4) D99(-30.798,-3.4) D100(-31.433,-3.4)
  round 0 hole 1 unplated paste-2539.97 mask+0.6: MH1(33.56,-2.3) MH2(-33.56,0)
  silkscreen extent -42.5,-50 42.5,4.8, body extent -34.31,-4.38 34.31,4.38, height 3.6
SAMTEC_FTSH-105-01-L-DV-007 [mm]
  rect 0.74x2.79 smd: 1(-2.54,-2.035) 2(-2.54,2.035) 3(-1.27,-2.035) 4(-1.27,2.035) 5(0,-2.035) 6(0,2.035) 8(1.27,2.035) 9(2.54,-2.035) 10(2.54,2.035)
  silkscreen extent -3.5,-2.3 3.26,1.72, body extent -3.19,-2.91 3.16,2.93, height 6.02
SAMTEC_LSS-130-03-L-DV-A-K-TR_ALT [mm] "For DSI mezzanine board"
  rect 0.4x1.6 smd: 1(9.207,-1.8) 2(9.207,1.8) 3(8.572,-1.8) 4(8.572,1.8) 5(7.938,-1.8) 6(7.938,1.8) 7(7.302,-1.8) 8(7.302,1.8) 9(6.667,-1.8) 10(6.667,1.8) 11(6.032,-1.8) 12(6.032,1.8) 13(5.397,-1.8) 14(5.397,1.8) 15(4.763,-1.8) 16(4.763,1.8) 17(4.127,-1.8) 18(4.127,1.8) 19(3.492,-1.8) 20(3.492,1.8) 21(2.858,-1.8) 22(2.857,1.8) 23(2.223,-1.8) 24(2.222,1.8) 25(1.588,-1.8) 26(1.587,1.8) 27(0.953,-1.8) 28(0.952,1.8) 29(0.318,-1.8) 30(0.317,1.8) 31(-0.317,-1.8) 32(-0.318,1.8) 33(-0.952,-1.8) 34(-0.953,1.8) 35(-1.587,-1.8) 36(-1.588,1.8) 37(-2.222,-1.8) 38(-2.223,1.8) 39(-2.857,-1.8) 40(-2.858,1.8) 41(-3.492,-1.8) 42(-3.492,1.8) 43(-4.127,-1.8) 44(-4.127,1.8) 45(-4.763,-1.8) 46(-4.763,1.8) 47(-5.397,-1.8) 48(-5.397,1.8) 49(-6.032,-1.8) 50(-6.032,1.8) 51(-6.667,-1.8) 52(-6.667,1.8) 53(-7.302,-1.8) 54(-7.302,1.8) 55(-7.938,-1.8) 56(-7.938,1.8) 57(-8.572,-1.8) 58(-8.572,1.8) 59(-9.207,-1.8) 60(-9.207,1.8)
  round 0.9 hole 0.9 unplated: ""(-10.275,1.1) ""(10.275,1.1)
  silkscreen extent -20,-43 20,7, body extent -11.9,-2.33 11.9,2.47, height 5.39
SD-4-B [mm] "SD Card Connector, 11 Positions, Connector, Push In, Pull Out, Surface Mount, 2.8 mm Height Above Board, Gold Flash"
  round 0 hole 1.2 unplated: 0(-11.5,5.325)
  round 0 hole 1.7 unplated: 0(9.5,5.325)
  rect 1x1.8 smd: 1(6.875,8.275) 2(4.375,8.275) 3(1.875,8.275) 4(-0.625,8.275) 5(-3.125,8.275) 6(-5.625,8.275) 7(-8.125,8.275) 8(-9.755,8.275) 9(9.375,8.275)
  rect 0.7x1.8 smd: 10(-11.055,8.275) 11(-12.255,8.275)
  rect 1.5x2.8 smd: 12(-13.65,-8.275) 12(-13.65,6.325) 12(11.42,6.325) 12(13.65,-8.275)
  silkscreen extent -13.5,-8.88 13.55,4.25, body extent -13.89,-9.28 13.76,8.73, height 3.52
SHORT_040 [mm]
  rrect50% 1.1x1 smd paste-2539.97 mask-2539.97: 1(-0.85,0) 2(0.85,0)
  Top Layer region: -1.143,-0.381 1.143,-0.381 1.143,0.381 -1.143,0.381
  Top Layer pour cut-out: -0.635,-0.508 0.635,-0.508 0.635,0.508 -0.635,0.508
SMAJ_TRANSIL [mm] "Diode SMA J-lead Transil / DO-214AC SMA"
  rect 1.4x1.64 smd: 1(-2.015,0) 2(2.015,0)
  silkscreen extent -2.95,-1.6 3.33,1.6, body extent -2.6,-1.3 2.6,1.3, height 2.4
SOD123_ALT [mm] "SOD-123; 2 Leads; Body 2.7 x 1.6 mm, (LxW)"
  rect 0.9x0.95 smd: 1(-1.575,0) 3(1.575,0)
  silkscreen extent -1.45,-0.85 1.45,0.85, body extent -1.85,-0.8 1.85,0.8, height 1.27
SOD523_SC79 [mm] "SOD-523; 2 Leads; Body 1.2 x 0.8 mm, (LxW)"
  rect 0.48x0.4 smd: 1(-0.675,0) 2(0.675,0)
  silkscreen extent -0.69,-0.55 0.69,0.55, body extent -0.8,-0.4 0.8,0.4, height 0.7
SOD923_DIO [mm] "Diode, SOD-923, CASE 514AA"
  rect 0.393x0.3 smd paste+0 mask+0: 1(-0.507,0) 2(0.507,0)
  Top Layer keep-out region: -0.15,-0.249 -0.15,0.249 0.15,0.249 0.15,-0.249
  body extent -0.53,-0.32 0.53,0.32, height 0.43
SOIC-8 [mil] "8-SOIC (0.154\", 3.90mm Width)"
  rrect50% 75x25 smd paste+0 mask+2.76: 1(-107.5,75) 2(-107.5,25) 3(-107.5,-25) 4(-107.5,-75) 5(107.5,-75) 6(107.5,-25) 7(107.5,25) 8(107.5,75)
  silkscreen extent -67,-100 35,110, body extent -118,-96 118,96, height 67
SOIC-16 [mm] "SOIC127P1030X265-16M_[SOIC-16W]_JEDEC_MS-013AA"
  rect 0.6x1.9 smd: 1(-4.445,-4.75) 2(-3.175,-4.75) 3(-1.905,-4.75) 4(-0.635,-4.75) 5(0.635,-4.75) 6(1.905,-4.75) 7(3.175,-4.75) 8(4.445,-4.75) 9(4.445,4.75) 10(3.175,4.75) 11(1.905,4.75) 12(0.635,4.75) 13(-0.635,4.75) 14(-1.905,4.75) 15(-3.175,4.75) 16(-4.445,4.75)
  silkscreen extent -5.42,-4.87 5.23,3.4, body extent -5.25,-5.32 5.25,5.32, height 2.66
SOP50P326X110-16N [mm] "16-SOT-23-THIN"
  rect 1.075x0.3 smd mask+0.05: 1(-1.538,1.75) 2(-1.538,1.25) 3(-1.538,0.75) 4(-1.538,0.25) 5(-1.538,-0.25) 6(-1.538,-0.75) 7(-1.538,-1.25) 8(-1.538,-1.75) 9(1.538,-1.75) 10(1.538,-1.25) 11(1.538,-0.75) 12(1.538,-0.25) 13(1.538,0.25) 14(1.538,0.75) 15(1.538,1.25) 16(1.538,1.75)
  silkscreen extent -1.67,-2.1 0.65,2.32, body extent -1.63,-2.1 1.63,2.1, height 0.97
"SOP-9 TP_ALT" [mm] "SOIC, 8-Leads, Body 5,0x4,0mm (max), Pitch 1,27mm, IPC Medium Density"
  rect 1.505x0.802 smd: 1(-2.5,1.905) 2(-2.5,0.635) 3(-2.5,-0.635) 4(-2.5,-1.905) 5(2.5,-1.905) 6(2.5,-0.635) 7(2.5,0.635) 8(2.5,1.905)
  rect 2.613x3.502 smd paste-1.307: 9(0,0)
  silkscreen extent -2.52,-2.5 0.9,2.88, body extent -3,-2.45 3,2.45, height 1.45
SOT23 [mm]
  rrect50% 0.85x1 smd: 1(-0.95,-1.2) 2(0.95,-1.2) 3(0,1.2)
  silkscreen extent -1.9,-1.32 1.28,1.2, body extent -1.45,-1.4 1.45,1.4, height 1.3
SOT23-5AN [mm] "SOT23, 5-Leads, Body 2.9x1.6mm, Pitch 0.95mm, Lead Span 2.8mm, IPC Medium Density"
  rect 1.1x0.65 smd: 1(-1.2,0.95) 2(-1.2,0) 3(-1.2,-0.95) 4(1.2,-0.95) 5(1.2,0.95)
  silkscreen extent -1.32,-1.55 0.25,1.95, body extent -1.4,-1.45 1.4,1.45, height 1.45
SOT23-6 [mm]
  rrect25% 0.58x1.21 smd paste+0 mask+0.1: 1(-0.95,-1.255) 2(0,-1.255) 3(0.95,-1.255) 4(0.95,1.255) 5(0,1.255) 6(-0.95,1.255)
  silkscreen extent -1.73,-1.37 1.56,0.8, body extent -1.45,-1.4 1.45,1.4, height 1.45
SOT23_M [mm]
  rrect50% 1.6x0.6 smd: 1(-1.1,0.95) 2(-1.1,-0.95) 3(1.1,0)
  silkscreen extent -1.22,-1.5 0.7,1.93, body extent -1.4,-1.45 1.4,1.45, height 1.3
SOT23_N [mm] "SOT23, 3-Leads, Body 2.9x1.3mm, Pitch 0.95mm, Lead Span 2.3mm, IPC Medium Density"
  rrect50% 1.3x0.6 smd: 1(-1.05,0.95) 2(-1.05,-0.95) 3(1.05,0)
  silkscreen extent -1.17,-1.5 0.7,1.92, body extent -1.4,-1.45 1.4,1.45, height 1.3
SOT223 [mm]
  rect 1.05x2.15 smd: 1(-2.3,-3.1) 2(0,-3.1) 3(2.3,-3.1)
  rect 3.4x2.15 smd: 4(0,3.1)
  silkscreen extent -3.47,-3.73 3.35,1.62, body extent -3.35,-3.6 3.35,3.6, height 1.9
SOT353-5N [mm] "SOT353, SC70, 5-Leads, Body 2x1.3mm, Pitch 0.65mm, Lead Span 2.1mm, IPC Medium Density"
  rrect50% 0.85x0.4 smd: 1(-0.95,0.65) 2(-0.95,0) 3(-0.95,-0.65) 4(0.95,-0.65) 5(0.95,0.65)
  silkscreen extent -1.07,-1.1 0.18,1.32, body extent -1.2,-1.1 1.2,1.1, height 1.1
SOT563 [mm]
  rect 0.45x0.3 smd: 1(-0.675,0.5) 2(-0.675,0) 3(-0.675,-0.5) 4(0.675,-0.5) 5(0.675,0) 6(0.675,0.5)
  silkscreen extent -1.18,-0.66 0.24,0.66, body extent -0.81,-0.8 0.81,0.8, height 0.59
SOT-323 [mm] "SOT-323/SC-70; 3 Leads; Body 2.2 x 2.2 mm, inc. leads (LxW max)"
  rect 0.8x1.05 smd: 1(-0.65,-1.025) 2(0.65,-1.025) 3(0,1.025)
  silkscreen extent -1.52,-1.17 1.1,0.89, body extent -1.1,-1.12 1.1,1.12, height 1.1
SOT-723_0P85X1P25_ONS [mil] "SOT-723"
  rect 11x20 smd paste+0 mask+0: 1(-15.75,-22.5) 2(15.75,-22.5) 3(0,22.5)
  silkscreen extent -41,-30 30,22, body extent -25,-20 25,22, height 18
SOTFL50P160X60-6N [mm] "SOT-563, SOT-666"
  rrect35% 0.57x0.3 smd: 1(-0.79,0.5) 2(-0.79,0) 3(-0.79,-0.5) 4(0.79,-0.5) 5(0.79,0) 6(0.79,0.5)
  silkscreen extent -0.9,-0.8 0,1.1, body extent -0.81,-0.8 0.81,0.8, height 0.58
SWITCH_SLW-913535-2A-SMT [mm] "Surface Mount DPDT 12V 100mA Black SMD Slide Switches ROHS"
  rect 2.15x1.2 smd paste+0 mask+0: 1(2.925,2.5) 2(2.925,0) 3(2.925,-2.5) 4(-2.925,2.5) 5(-2.925,0) 6(-2.925,-2.5)
  silkscreen extent -1.93,-4.72 2.65,4.72, body extent -3.75,-4.55 3.75,4.55, height 6.55
T-PBGA-24 [mm] "BGA, 25-Leads, Body 6,00x8,00mmx1,10mm, Pitch 1,00mm"
  round 0.35 smd: A2(-1,2) A3(0,2) A4(1,2) A5(2,2) B1(-2,1) B2(-1,1) B3(0,1) B4(1,1) B5(2,1) C1(-2,0) C2(-1,0) C3(0,0) C4(1,0) C5(2,0) D1(-2,-1) D2(-1,-1) D3(0,-1) D4(1,-1) D5(2,-1) E1(-2,-2) E2(-1,-2) E3(0,-2) E4(1,-2) E5(2,-2)
  silkscreen extent -3.48,-4 3,4.54, body extent -3,-4 3,4, height 0.8
"T_AMPHENOL_ GSB311231HR" [mm]
  round 1 hole 0.7: L1(-3.5,-1.35) L2(-1,-1.35) L3(1,-1.35) L4(3.5,-1.35) L5(4,0.15) L6(2,0.15) L7(0,0.15) L8(-2,0.15) L9(-4,0.15) U1(-3.5,1.85) U2(-1,1.85) U3(1,1.85) U4(3.5,1.85) U5(4,3.35) U6(2,3.35) U7(0,3.35) U8(-2,3.35) U9(-4,3.35)
  round 2.9 hole 2.3: S1(-6.57,-3.35) S2(-6.57,2.33) S3(6.57,2.33) S4(6.57,-3.35)
  silkscreen extent -6.8,-10.9 6.8,4.72, body extent -7.79,-15.13 7.79,4.57, height 16.13
T_KEYSTONE_3030 [mm] "Battery Holder"
  rrect10% 4x4 smd paste-1000 mask+0: 1(0,0)
  rrect10% 2.9x3.5 smd paste+0: 2(-6.6,0) 2(6.6,0)
  silkscreen extent -5.44,-4.79 5.44,5.31, body extent -8.05,-5 8.05,5, height 3.2
TDK_MMICT5818-00-012 [mm]
  round 0 hole 0.5 unplated: 0(0.704,-0.025)
  rect 0.522x0.725 smd paste-0.008: 1(-1.369,-0.837) 2(-0.547,-0.837) 4(-0.547,0.838) 5(-1.369,0.838)
  rect 0.2x0.2 smd paste-0.508: 3(0.041,-0.027) 3(0.702,0.639) 3(0.708,-0.689) 3(1.369,-0.022)
  round 0.025 smd paste-1: 3(0.299,-0.431) 3(0.299,0.381) 3(1.111,0.381) 3(1.111,-0.431)
  Top Layer region: -0.107,-0.025 -0.046,0.286 0.131,0.55 0.394,0.726 0.705,0.788 0.705,0.788 0.705,0.488 0.448,0.419 0.261,0.232 0.192,-0.025 0.192,-0.025
  Top Layer region: 0.705,-0.837 0.394,-0.776 0.131,-0.6 -0.046,-0.336 -0.107,-0.025 -0.107,-0.025 0.192,-0.025 0.261,-0.282 0.449,-0.47 0.705,-0.538 0.705,-0.538
  Top Layer region: 1.518,-0.025 1.456,-0.336 1.28,-0.6 1.016,-0.776 0.705,-0.837 0.705,-0.837 0.705,-0.538 0.962,-0.469 1.15,-0.282 1.218,-0.025 1.218,-0.025
  Top Layer region: 0.704,0.787 1.015,0.726 1.279,0.55 1.456,0.286 1.518,-0.025 1.518,-0.025 1.218,-0.025 1.179,0.172 1.067,0.338 0.901,0.45 0.704,0.488 0.704,0.488
  silkscreen extent -1.85,-1.57 1.85,1.4, body extent -1.75,-1.33 1.75,1.33, height 0.98
TESTPOINT_1 [mm]
  round 1.3 hole 0.8: 1(0,0)
  silkscreen extent -0.9,-0.9 0.9,0.9
TESTPOINT_3 [mm]
  round 1.25 smd paste-1.25: 1(0,0)
TESTPOINT_4 [mil]
  round 125 hole 63: 1(0,0)
  silkscreen extent -76,-76 76,76, body extent -62,-63 62,63, height 320
TSOT26 [mm] "TSOT-26, SOT-23-6 Thin, TSOT-23-6"
  rect 1x0.7 smd paste+0 mask+0: 1(-1.3,0.95) 2(-1.3,0) 3(-1.3,-0.95) 4(1.3,-0.95) 5(1.3,0) 6(1.3,0.95)
  silkscreen extent -1.5,-1.63 0.98,1.7, body extent -1.45,-1.45 1.45,1.45, height 1
TSOT-23-8_ADI [mm] "TS8 Package ADI, 8-Lead Plastic TSOT-23"
  rect 1.22x0.45 smd paste-0.05: 1(-1.315,0.975) 2(-1.315,0.325) 3(-1.315,-0.325) 4(-1.315,-0.975) 5(1.315,-0.975) 6(1.315,-0.325) 7(1.315,0.325) 8(1.315,0.975)
  silkscreen extent -1.46,-1.6 0.95,1.71, body extent -1.4,-1.45 1.4,1.45, height 1
TSSO3X5-G8/X.35 [mm] "TSSOP-8P065 Shrink Small Outline; 8 Leads; Body Width 3 mm; Pitch 0.65 mm"
  rrect25% 0.4x1.42 smd paste+0 mask+0.07: 1(-0.975,-1.77) 2(-0.325,-1.77) 3(0.325,-1.77) 4(0.975,-1.77) 5(0.975,1.77) 6(0.325,1.77) 7(-0.325,1.77) 8(-0.975,1.77)
  silkscreen extent -1.65,-2.11 1.52,0.8, body extent -1.47,-2 1.47,2, height 1.3
TSSOP8 [mm] "Shrink Small Outline; 8 Leads; Body Width 3 mm; Pitch 0.65 mm"
  rect 0.4x1.5 smd: 1(-0.975,-2.9) 2(-0.325,-2.9) 3(0.325,-2.9) 4(0.975,-2.9) 5(0.975,2.9) 6(0.325,2.9) 7(-0.325,2.9) 8(-0.975,2.9)
  silkscreen extent -1.65,-3 1.52,1.89, body extent -1.5,-3.2 1.5,3.2, height 1.2
TSSOP14 [mm] "14-Lead Thin Shrink Small Outline Package (TSSOP), JEDEC MO-153, 5.0x4.4mm Wide, Pitch 0.65"
  rect 1.41x0.356 smd: 1(-2.95,1.95) 2(-2.95,1.3) 3(-2.95,0.65) 4(-2.95,0) 5(-2.95,-0.65) 6(-2.95,-1.3) 7(-2.95,-1.95) 8(2.95,-1.95) 9(2.95,-1.3) 10(2.95,-0.65) 11(2.95,0) 12(2.95,0.65) 13(2.95,1.3) 14(2.95,1.95)
  silkscreen extent -3.35,-2.27 1.59,2.55, body extent -3.3,-2.55 3.3,2.55, height 1.2
TSSOP16 [mm] "PW0016A (TI)"
  rrect50% 1.5x0.45 smd mask+0.05: 1(-2.9,2.275) 2(-2.9,1.625) 3(-2.9,0.975) 4(-2.9,0.325) 5(-2.9,-0.325) 6(-2.9,-0.975) 7(-2.9,-1.625) 8(-2.9,-2.275) 9(2.9,-2.275) 10(2.9,-1.625) 11(2.9,-0.975) 12(2.9,-0.325) 13(2.9,0.325) 14(2.9,0.975) 15(2.9,1.625) 16(2.9,2.275)
  silkscreen extent -3.02,-2.55 1.55,3.02, body extent -3.3,-2.55 3.3,2.55, height 1.2
TSSOP16_NXP [mm] "SOT403-1 (NXP)"
  rrect50% 1.5x0.4 smd mask+0.05: 1(-2.95,2.275) 2(-2.95,1.625) 3(-2.95,0.975) 4(-2.95,0.325) 5(-2.95,-0.325) 6(-2.95,-0.975) 7(-2.95,-1.625) 8(-2.95,-2.275) 9(2.95,-2.275) 10(2.95,-1.625) 11(2.95,-0.975) 12(2.95,-0.325) 13(2.95,0.325) 14(2.95,0.975) 15(2.95,1.625) 16(2.95,2.275)
  silkscreen extent -3.02,-2.55 1.55,3.02, body extent -3.21,-2.5 3.21,2.5, height 0.98
U-DFN1616-6 [mm] "6-UFDFN Exposed Pad, 1.6 x 1.6 mm"
  rect 0.525x0.3 smd: 1(-0.69,0.5) 2(-0.69,0) 3(-0.69,-0.5) 4(0.69,-0.5) 5(0.69,0) 6(0.69,0.5)
  rect 0.5x1.3 smd: 7(0,0)
  silkscreen extent -1.81,-1.13 0.47,1.13, body extent -1.05,-1 1.05,1, height 0.75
